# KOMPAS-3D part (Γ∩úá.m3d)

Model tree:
1. Эскиз:1
2. Операция выдавливания:1
     Расстояние 1 = 4; Расстояние 2 = 2
3. Эскиз:2
4. Операция выдавливания:2
     Расстояние 1 = 4; Расстояние 2 = 4
5. Скругление:1
     Радиус = 2

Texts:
  Сплав АЛ8  ГОСТ 1583-93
